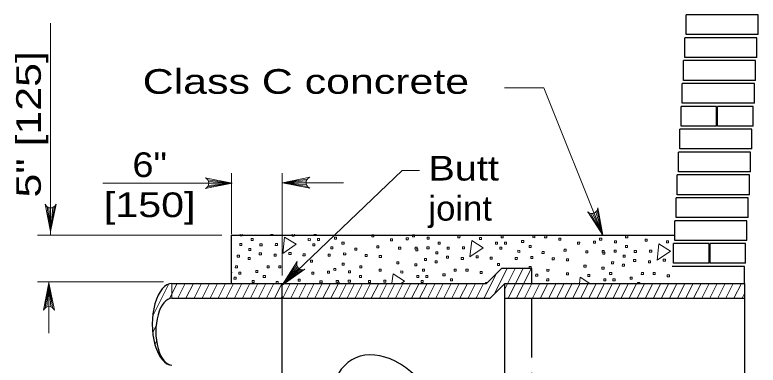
# Model space of a CAD drawing. Extents: x 750.7 to 784.7, y 860.1 to 882.1.
# Drawn here: x 758.48 to 763.303, y 876.32 to 878.591 of the extents above; entities that cross this region are included whole.
import ezdxf
from ezdxf.enums import TextEntityAlignment as Align

# ---------------------------------------------------------------- set-up
doc = ezdxf.new("R2010")
doc.units = 0
doc.header["$LTSCALE"] = 0.064
doc.linetypes.add('LONG_DASHED', pattern=[7.5, 6, -1.5])
doc.layers.add('1', color=7, linetype='Continuous', lineweight=13)

msp = doc.modelspace()

# ---------------------------------------------------------------- linework, layer by layer
at = {"layer": '1'}
for p, q in [((758.71192, 877.16183), (758.71192, 878.53658)), ((759.885, 877.16933), (759.885, 877.56492)), ((760.21358, 876.90092), (760.21358, 877.56492)), ((759.89083, 877.49983), (759.05142, 877.49983)), ((759.72867, 877.475), (759.89083, 877.49983)), ((759.7305, 877.52225), (759.89083, 877.49983)), ((759.73475, 877.48542), (759.89083, 877.49983)), ((759.736, 877.51117), (759.89083, 877.49983)), ((759.73758, 877.49983), (759.89083, 877.49983)), ((760.37617, 877.52533), (760.21583, 877.50292)), ((760.37075, 877.51425), (760.21583, 877.50292)), ((760.6125, 877.50292), (760.21583, 877.50292)), ((760.36908, 877.50292), (760.21583, 877.50292)), ((760.37192, 877.4885), (760.21583, 877.50292)), ((760.378, 877.47817), (760.21583, 877.50292)), ((758.6895, 877.34592), (758.71192, 877.18558)), ((758.73667, 877.34783), (758.71192, 877.18558)), ((758.70058, 877.3405), (758.71192, 877.18558)), ((758.72625, 877.34167), (758.71192, 877.18558)), ((758.71192, 877.33883), (758.71192, 877.18558)), ((762.21467, 877.30375), (762.29442, 877.16292)), ((762.227, 877.30283), (762.29442, 877.16292)), ((762.23808, 877.30542), (762.29442, 877.16292)), ((762.2505, 877.31333), (762.29442, 877.16292)), ((762.25792, 877.32283), (762.29442, 877.16292)), ((758.62633, 877.16183), (759.82325, 877.16183)), ((761.07608, 877.07258), (761.07625, 877.085)), ((762.29033, 877.05058), (762.2905, 877.06308)), ((760.30908, 876.96983), (760.21358, 876.83908)), ((760.31325, 876.95817), (760.21358, 876.83908)), ((760.32025, 876.94908), (760.21358, 876.83908)), ((760.33258, 876.94108), (760.21358, 876.83908)), ((760.34433, 876.93833), (760.21358, 876.83908)), ((761.52467, 876.75375), (761.60533, 876.91508)), ((761.59042, 876.78075), (761.67317, 876.94617)), ((761.659, 876.81325), (761.72542, 876.94617)), ((761.6815, 876.75375), (761.77775, 876.94617)), ((761.73383, 876.75375), (761.83, 876.94617)), ((760.56567, 876.85592), (760.56575, 876.86833)), ((760.93383, 876.91167), (760.92692, 876.85025)), ((762.14808, 876.88975), (762.14358, 876.84992)), ((762.21067, 876.84992), (762.14808, 876.88975)), ((759.44425, 876.85983), (758.62633, 876.85983)), ((758.67667, 876.69058), (758.7015, 876.85275)), ((758.68708, 876.69667), (758.7015, 876.85275)), ((758.7015, 876.527), (758.7015, 876.85983)), ((758.7015, 876.6995), (758.7015, 876.85275)), ((758.71283, 876.69792), (758.7015, 876.85275)), ((758.72392, 876.69242), (758.7015, 876.85275)), ((759.374, 876.63542), (759.47967, 876.84683)), ((759.48433, 876.7515), (759.53358, 876.84992)), ((759.49933, 876.75375), (759.49933, 876.84992)), ((759.53775, 876.75383), (759.58583, 876.84992)), ((759.59017, 876.75392), (759.63817, 876.84992)), ((759.6425, 876.754), (759.69042, 876.84992)), ((759.69483, 876.75417), (759.74267, 876.84992)), ((759.74717, 876.75425), (759.795, 876.84992)), ((759.7995, 876.75442), (759.84725, 876.84992)), ((759.85183, 876.7545), (759.89958, 876.84992)), ((759.90417, 876.75458), (759.95183, 876.84992)), ((759.9565, 876.75475), (760.00417, 876.84992)), ((760.00883, 876.75483), (760.05642, 876.84992)), ((760.06125, 876.75492), (760.10875, 876.84992)), ((760.11358, 876.75508), (760.161, 876.84992)), ((760.16592, 876.75517), (760.21325, 876.84992)), ((760.1755, 876.85325), (760.17558, 876.86117)), ((760.21358, 876.746), (760.26558, 876.84992)), ((760.26975, 876.75375), (760.31783, 876.84992)), ((760.32208, 876.75375), (760.37017, 876.84992)), ((760.37433, 876.75375), (760.42242, 876.84992)), ((760.42658, 876.75375), (760.47475, 876.84992)), ((760.47892, 876.75375), (760.527, 876.84992)), ((760.53117, 876.75375), (760.57933, 876.84992)), ((760.57017, 876.85033), (760.57025, 876.85783)), ((760.5835, 876.75375), (760.63158, 876.84992)), ((760.63575, 876.75375), (760.68383, 876.84992)), ((760.68808, 876.75375), (760.73617, 876.84992)), ((760.74033, 876.75375), (760.78842, 876.84992)), ((760.79267, 876.75375), (760.84075, 876.84992)), ((760.84492, 876.75375), (760.893, 876.84992)), ((760.89717, 876.75375), (760.94533, 876.84992)), ((760.9495, 876.75375), (760.99758, 876.84992)), ((761.00175, 876.75375), (761.04992, 876.84992)), ((761.05408, 876.75375), (761.10217, 876.84992)), ((761.10633, 876.75375), (761.15442, 876.84992)), ((761.15867, 876.75375), (761.20675, 876.84992)), ((761.21092, 876.75375), (761.259, 876.84992)), ((761.26325, 876.75375), (761.31133, 876.84992)), ((761.3155, 876.75375), (761.36358, 876.84992)), ((761.36775, 876.75375), (761.41592, 876.84992)), ((761.42008, 876.75375), (761.46817, 876.84992)), ((761.47233, 876.75375), (761.5205, 876.84992)), ((761.53258, 876.85467), (761.545, 876.85458)), ((761.53258, 876.84992), (761.53258, 876.85467)), ((761.78608, 876.75375), (761.83417, 876.84992)), ((761.83692, 876.75075), (761.8865, 876.84992)), ((761.88925, 876.75083), (761.93875, 876.84992)), ((761.94158, 876.751), (761.99108, 876.84992)), ((761.99392, 876.75108), (762.04333, 876.84992)), ((762.04625, 876.75117), (762.09558, 876.84992)), ((762.09858, 876.75133), (762.14792, 876.84992)), ((762.15092, 876.75142), (762.20017, 876.84992)), ((762.20325, 876.7515), (762.2525, 876.84992)), ((762.25567, 876.75167), (762.30475, 876.84992)), ((762.308, 876.75175), (762.35708, 876.84992)), ((762.36033, 876.75192), (762.40933, 876.84992)), ((762.41267, 876.752), (762.46167, 876.84992)), ((762.465, 876.75208), (762.51392, 876.84992)), ((762.51733, 876.75225), (762.56617, 876.84992)), ((762.52042, 876.84992), (762.5205, 876.85642)), ((762.56967, 876.75233), (762.6185, 876.84992)), ((762.622, 876.75242), (762.67075, 876.84992)), ((762.67442, 876.75258), (762.72308, 876.84992)), ((762.72675, 876.75267), (762.77533, 876.84992)), ((762.77908, 876.75275), (762.82767, 876.84992)), ((762.83142, 876.75292), (762.87992, 876.84992)), ((762.88375, 876.753), (762.93225, 876.84992)), ((762.93642, 876.75375), (762.9845, 876.84992)), ((762.98867, 876.75375), (763.03675, 876.84992)), ((763.041, 876.75375), (763.08908, 876.84992)), ((763.09325, 876.75375), (763.14133, 876.84992)), ((763.14558, 876.75375), (763.19367, 876.84992)), ((763.19783, 876.75375), (763.21333, 876.78467)), ((759.37433, 876.53142), (759.39658, 876.57592)), ((759.38817, 876.45458), (759.399, 876.47617)), ((759.4105, 876.39458), (759.41608, 876.40575)), ((759.44042, 876.34975), (759.44275, 876.35442))]:
    msp.add_line(p, q, dxfattribs=at)
at = {"layer": '1', "lineweight": 25}
for p, q in [((762.80233, 877.86975), (762.80233, 877.99783)), ((763.03992, 877.86975), (763.03992, 877.99783)), ((763.0325, 877.86975), (762.80233, 877.86975)), ((763.27, 877.86975), (763.03992, 877.86975)), ((759.885, 876.84992), (759.885, 877.16183)), ((759.885, 877.16183), (762.76183, 877.16183)), ((762.75375, 876.98017), (762.75375, 877.10825)), ((762.99125, 876.98017), (762.99125, 877.10825)), ((762.98383, 876.98017), (762.75375, 876.98017)), ((763.22142, 876.98017), (762.99125, 876.98017)), ((761.63658, 876.94617), (761.54033, 876.84992)), ((761.8345, 876.94617), (761.63658, 876.94617)), ((761.8345, 876.84992), (761.8345, 876.94617)), ((759.49933, 876.84992), (760.21358, 876.84992)), ((760.21358, 876.84992), (761.54033, 876.84992)), ((760.21367, 875.89692), (760.21358, 876.83908)), ((761.65925, 876.84992), (761.56308, 876.75375)), ((761.65933, 875.88608), (761.65925, 876.84992)), ((761.65933, 875.88617), (761.65925, 876.84992)), ((761.65925, 876.84992), (763.21333, 876.84992)), ((763.21333, 876.84992), (763.21333, 876.75367)), ((759.49933, 876.75367), (760.20417, 876.75375)), ((760.22308, 876.75375), (761.56308, 876.75375)), ((761.65925, 876.75375), (763.21333, 876.75375)), ((763.21333, 876.75375), (763.21333, 875.98958))]:
    msp.add_line(p, q, dxfattribs=at)
at = {"layer": '1', "linetype": 'LONG_DASHED', "lineweight": 25}
msp.add_line((761.8345, 875.88617), (761.8345, 876.84992), dxfattribs=at)
at = {"layer": '1', "lineweight": 25}
for points in [[(763.3025, 878.46283), (763.3025, 878.59092), (762.83475, 878.59092)], [(763.3025, 878.46283), (762.83475, 878.46283), (762.83475, 878.59092)], [(763.29433, 878.31458), (763.29433, 878.44267), (762.82667, 878.44267)], [(763.29433, 878.31458), (762.82667, 878.31458), (762.82667, 878.44267)], [(763.28625, 878.16633), (763.28625, 878.29433), (762.81858, 878.29433)], [(763.28625, 878.16633), (762.81858, 878.16633), (762.81858, 878.29433)], [(763.27817, 878.01808), (763.27817, 878.14608), (762.8105, 878.14608)], [(763.27817, 878.01808), (762.8105, 878.01808), (762.8105, 878.14608)], [(763.0325, 877.86975), (763.0325, 877.99783), (762.80233, 877.99783)], [(763.27, 877.86975), (763.27, 877.99783), (763.03992, 877.99783)], [(763.26192, 877.7215), (763.26192, 877.84958), (762.79425, 877.84958)], [(763.26192, 877.7215), (762.79425, 877.7215), (762.79425, 877.84958)], [(763.25383, 877.57325), (763.25383, 877.70133), (762.78617, 877.70133)], [(763.25383, 877.57325), (762.78617, 877.57325), (762.78617, 877.70133)], [(763.24575, 877.425), (763.24575, 877.553), (762.77808, 877.553)], [(763.24575, 877.425), (762.77808, 877.425), (762.77808, 877.553)], [(763.23758, 877.27675), (763.23758, 877.40475), (762.76992, 877.40475)], [(763.23758, 877.27675), (762.76992, 877.27675), (762.76992, 877.40475)], [(763.2295, 877.12842), (763.2295, 877.2565), (762.76183, 877.2565)], [(763.2295, 877.12842), (762.76183, 877.12842), (762.76183, 877.2565)], [(762.98383, 876.98017), (762.98383, 877.10825), (762.75375, 877.10825)], [(763.22142, 876.98017), (763.22142, 877.10825), (762.99125, 877.10825)], [(763.21333, 876.84992), (763.21333, 876.96), (762.74567, 876.96)]]:
    msp.add_lwpolyline(points, dxfattribs=at)
at = {"layer": '1'}
for points in [[(762.29442, 877.16292), (761.91233, 878.11767), (761.65675, 878.11767)], [(760.21358, 876.83908), (760.99383, 877.58225), (761.10458, 877.58225)], [(759.71375, 877.46442), (759.89083, 877.49983), (759.71375, 877.53525)], [(760.39292, 877.4675), (760.21583, 877.50292), (760.39292, 877.53833)], [(758.74733, 877.36267), (758.71192, 877.18558), (758.6765, 877.36267)], [(762.26225, 877.34058), (762.29442, 877.16292), (762.1965, 877.31458)], [(759.95483, 877.16917), (759.95467, 877.15767), (759.94108, 877.15775), (759.94117, 877.16917)], [(760.15392, 877.16867), (760.15392, 877.16675), (760.14025, 877.16683), (760.14025, 877.16867)], [(760.29333, 877.16825), (760.29325, 877.15583), (760.27958, 877.15592), (760.27975, 877.16833)], [(760.4345, 877.16792), (760.4345, 877.16733), (760.42092, 877.16742), (760.42092, 877.16792)], [(761.07625, 877.085), (761.08992, 877.08492), (761.08983, 877.07842)], [(762.2905, 877.06308), (762.30408, 877.06292), (762.30408, 877.05642)], [(760.36233, 876.94158), (760.21358, 876.83908), (760.31142, 876.99092)], [(759.885, 876.92308), (759.88675, 876.92308), (759.88658, 876.91017), (759.885, 876.91017)], [(760.56575, 876.86833), (760.57942, 876.86825), (760.57942, 876.86175)], [(760.98733, 876.85017), (761.00833, 876.86442), (760.93383, 876.91167)], [(758.66608, 876.67567), (758.7015, 876.85275), (758.73692, 876.67567)], [(760.17558, 876.86117), (760.18917, 876.86108), (760.18908, 876.85333)], [(760.57025, 876.85783), (760.58383, 876.85775), (760.58383, 876.85033)], [(762.5205, 876.85642), (762.53408, 876.85633), (762.53408, 876.84992)]]:
    msp.add_lwpolyline(points, dxfattribs=at)
for points in [[(760.79525, 877.16508), (760.80883, 877.16492), (760.80875, 877.15208), (760.79508, 877.15217)], [(761.05958, 877.16417), (761.07325, 877.164), (761.07308, 877.15108), (761.0595, 877.15125)], [(761.35467, 877.15775), (761.36825, 877.15767), (761.36808, 877.14475), (761.3545, 877.14483)], [(761.63525, 877.15842), (761.64892, 877.15825), (761.64875, 877.14533), (761.63517, 877.1455)], [(761.841, 877.15925), (761.85467, 877.15917), (761.8545, 877.14625), (761.84092, 877.14633)], [(761.9175, 877.15858), (761.93117, 877.1585), (761.931, 877.14558), (761.91742, 877.14575)], [(762.44258, 877.15767), (762.45625, 877.15758), (762.45608, 877.14467), (762.4425, 877.14475)], [(759.93967, 877.10908), (759.95325, 877.109), (759.95317, 877.09608), (759.9395, 877.09617)], [(760.01258, 877.14008), (760.02625, 877.13992), (760.02608, 877.127), (760.01242, 877.12717)], [(760.0705, 877.107), (760.08417, 877.10692), (760.084, 877.094), (760.07042, 877.09408)], [(760.17017, 877.109), (760.18375, 877.10892), (760.18367, 877.096), (760.17, 877.09608)], [(760.23008, 877.15033), (760.21817, 877.04467), (760.30458, 877.10308)], [(760.38358, 877.13983), (760.39717, 877.13975), (760.39708, 877.12683), (760.38342, 877.12692)], [(760.41242, 877.10642), (760.42608, 877.10625), (760.42592, 877.09333), (760.41233, 877.0935)], [(760.44275, 877.14008), (760.45633, 877.14), (760.45625, 877.12708), (760.44258, 877.12717)], [(760.55383, 877.15033), (760.56742, 877.15017), (760.56733, 877.13725), (760.55367, 877.13742)], [(760.6025, 877.11708), (760.61617, 877.117), (760.616, 877.10408), (760.60233, 877.10417)], [(760.91683, 877.13975), (760.93042, 877.13958), (760.93033, 877.12667), (760.91667, 877.12683)], [(761.01942, 877.14475), (761.033, 877.14467), (761.03292, 877.13175), (761.01925, 877.13192)], [(761.15542, 877.14867), (761.16908, 877.14858), (761.16892, 877.13567), (761.15533, 877.13575)], [(761.22683, 877.11808), (761.24042, 877.118), (761.24033, 877.10508), (761.22667, 877.10517)], [(761.44433, 877.12842), (761.43242, 877.02267), (761.51883, 877.08108)], [(761.494, 877.14683), (761.50758, 877.14675), (761.50742, 877.13383), (761.49383, 877.13392)], [(761.59775, 877.11783), (761.61142, 877.11775), (761.61125, 877.10483), (761.59767, 877.10492)], [(761.657, 877.11808), (761.67058, 877.118), (761.6705, 877.10508), (761.65683, 877.10517)], [(761.76808, 877.12833), (761.78167, 877.12825), (761.78158, 877.11533), (761.76792, 877.11542)], [(762.0095, 877.14308), (762.02308, 877.143), (762.023, 877.13008), (762.00933, 877.13017)], [(762.131, 877.11775), (762.14467, 877.11767), (762.1445, 877.10475), (762.13092, 877.10483)], [(762.23358, 877.12283), (762.24725, 877.12275), (762.24708, 877.10983), (762.2335, 877.10992)], [(762.27383, 877.14217), (762.2875, 877.142), (762.28733, 877.12917), (762.27367, 877.12925)], [(762.36967, 877.12667), (762.38325, 877.12658), (762.38317, 877.11367), (762.3695, 877.11375)], [(762.56883, 877.13575), (762.5825, 877.13567), (762.58233, 877.12275), (762.56875, 877.12283)], [(762.6585, 877.10642), (762.64667, 877.00067), (762.733, 877.05908)], [(762.70817, 877.12483), (762.72183, 877.12475), (762.72167, 877.11183), (762.70808, 877.11192)], [(759.99758, 877.076), (760.01117, 877.07592), (760.01108, 877.063), (759.99742, 877.06308)], [(760.52958, 877.08617), (760.54317, 877.086), (760.54308, 877.07308), (760.52942, 877.07325)], [(760.68608, 877.07792), (760.69967, 877.07775), (760.6995, 877.06483), (760.68592, 877.065)], [(760.82883, 877.09333), (760.8425, 877.09325), (760.84233, 877.08033), (760.82875, 877.08042)], [(760.96983, 877.08375), (760.98342, 877.08367), (760.98333, 877.07075), (760.96967, 877.07083)], [(761.08075, 877.0745), (761.09433, 877.07442), (761.09425, 877.0615), (761.08058, 877.06158)], [(761.15383, 877.08708), (761.1675, 877.087), (761.16733, 877.07408), (761.15375, 877.07417)], [(761.28475, 877.085), (761.29833, 877.08492), (761.29825, 877.072), (761.28458, 877.07208)], [(761.38442, 877.087), (761.398, 877.08692), (761.39783, 877.074), (761.38425, 877.07408)], [(761.62667, 877.08442), (761.64025, 877.08433), (761.64017, 877.07142), (761.6265, 877.0715)], [(761.74375, 877.06417), (761.75742, 877.06408), (761.75725, 877.05117), (761.74367, 877.05125)], [(761.81675, 877.09508), (761.83033, 877.095), (761.83025, 877.08208), (761.81658, 877.08217)], [(762.04308, 877.07133), (762.05675, 877.07125), (762.05658, 877.05833), (762.04292, 877.05842)], [(762.184, 877.06175), (762.19767, 877.06167), (762.1975, 877.04875), (762.18392, 877.04883)], [(762.36808, 877.06508), (762.38175, 877.065), (762.38158, 877.05208), (762.368, 877.05225)], [(762.441, 877.09608), (762.45467, 877.096), (762.4545, 877.08308), (762.44092, 877.08317)], [(762.499, 877.063), (762.51258, 877.06292), (762.5125, 877.05), (762.49883, 877.05008)], [(762.59858, 877.065), (762.61225, 877.06492), (762.61208, 877.052), (762.5985, 877.05208)], [(759.92325, 877.03367), (759.93683, 877.03358), (759.93667, 877.02067), (759.92308, 877.02075)], [(759.993, 877.01792), (760.00667, 877.01775), (760.0065, 877.00483), (759.99292, 877.005)], [(760.066, 877.04883), (760.07958, 877.04875), (760.0795, 877.03583), (760.06583, 877.03592)], [(760.16217, 877.03975), (760.17583, 877.03958), (760.17567, 877.02667), (760.16208, 877.02683)], [(760.25842, 877.05025), (760.27208, 877.05017), (760.27192, 877.03725), (760.25833, 877.03733)], [(760.34967, 877.04208), (760.36325, 877.042), (760.36317, 877.02908), (760.3495, 877.02917)], [(760.51242, 877.03958), (760.526, 877.0395), (760.52592, 877.02658), (760.51225, 877.02667)], [(760.61308, 877.04692), (760.62675, 877.04683), (760.62658, 877.03392), (760.613, 877.034)], [(760.75242, 877.03758), (760.766, 877.0375), (760.76592, 877.02458), (760.75225, 877.02467)], [(760.84433, 877.03017), (760.858, 877.03008), (760.85783, 877.01717), (760.84417, 877.01733)], [(761.13742, 877.01167), (761.15108, 877.01158), (761.15092, 876.99867), (761.13733, 876.99875)], [(761.21183, 877.054), (761.22542, 877.05392), (761.22533, 877.041), (761.21167, 877.04117)], [(761.28017, 877.02683), (761.29383, 877.02675), (761.29367, 877.01383), (761.28008, 877.01392)], [(761.37642, 877.01775), (761.39, 877.01767), (761.38992, 877.00475), (761.37625, 877.00483)], [(761.47267, 877.02825), (761.48633, 877.02817), (761.48617, 877.01525), (761.47258, 877.01533)], [(761.56383, 877.02008), (761.5775, 877.02), (761.57733, 877.00708), (761.56375, 877.00717)], [(761.72658, 877.01758), (761.74025, 877.0175), (761.74008, 877.00458), (761.7265, 877.00467)], [(761.82733, 877.02492), (761.84092, 877.02483), (761.84083, 877.01192), (761.82717, 877.012)], [(761.90025, 877.05592), (761.91392, 877.05583), (761.91375, 877.04292), (761.90017, 877.043)], [(761.96658, 877.01567), (761.98025, 877.0155), (761.98008, 877.00258), (761.9665, 877.00275)], [(762.29492, 877.0525), (762.30858, 877.05242), (762.30842, 877.0395), (762.29483, 877.03958)], [(762.426, 877.03208), (762.43967, 877.03192), (762.4395, 877.019), (762.42592, 877.01917)], [(759.91058, 876.96367), (759.92417, 876.96358), (759.92408, 876.95067), (759.91042, 876.95075)], [(760.11633, 876.96458), (760.12992, 876.9645), (760.12983, 876.95158), (760.11617, 876.95167)], [(760.19283, 876.96392), (760.20642, 876.96383), (760.20633, 876.95092), (760.19267, 876.951)], [(760.39758, 877.00008), (760.41117, 876.99992), (760.411, 876.987), (760.39742, 876.98717)], [(760.60308, 876.98192), (760.61667, 876.98183), (760.6165, 876.96892), (760.60292, 876.969)], [(760.71792, 876.963), (760.7315, 876.96283), (760.73142, 876.94992), (760.71775, 876.95008)], [(760.958, 876.99017), (760.97167, 876.99), (760.9715, 876.97708), (760.95792, 876.97725)], [(761.075, 876.9775), (761.08867, 876.97742), (761.0885, 876.9645), (761.07492, 876.96458)], [(761.20725, 876.99592), (761.22083, 876.99575), (761.22075, 876.98292), (761.20708, 876.983)], [(761.61175, 876.97808), (761.62542, 876.97792), (761.62525, 876.96508), (761.61167, 876.96517)], [(762.05858, 877.00825), (762.07217, 877.00808), (762.07208, 876.99525), (762.05842, 876.99533)], [(762.17225, 876.96817), (762.18592, 876.968), (762.18575, 876.95517), (762.17217, 876.95525)], [(762.35167, 876.98975), (762.36525, 876.98958), (762.36517, 876.97667), (762.3515, 876.97683)], [(762.4215, 876.97392), (762.43508, 876.97383), (762.435, 876.96092), (762.42133, 876.961)], [(762.49442, 877.00483), (762.50808, 877.00475), (762.50792, 876.99183), (762.49425, 876.992)], [(762.59067, 876.99575), (762.60425, 876.99567), (762.60408, 876.98275), (762.5905, 876.98283)], [(762.68692, 877.00625), (762.7005, 877.00617), (762.70042, 876.99325), (762.68675, 876.99342)], [(759.93225, 876.92342), (759.94592, 876.92325), (759.94575, 876.91042), (759.93217, 876.9105)], [(760.04333, 876.93358), (760.057, 876.9335), (760.05683, 876.92058), (760.04325, 876.92067)], [(760.40633, 876.923), (760.42, 876.92292), (760.41983, 876.91), (760.40617, 876.91008)], [(760.50892, 876.92808), (760.5225, 876.928), (760.52242, 876.91508), (760.50875, 876.91517)], [(760.54917, 876.94742), (760.56275, 876.94733), (760.56267, 876.93442), (760.549, 876.9345)], [(760.645, 876.932), (760.65858, 876.93192), (760.65842, 876.919), (760.64483, 876.91908)], [(760.84417, 876.94108), (760.85775, 876.941), (760.85767, 876.92808), (760.844, 876.92817)], [(760.9835, 876.93017), (760.99708, 876.93008), (760.997, 876.91717), (760.98333, 876.91725)], [(761.12475, 876.94167), (761.13842, 876.94158), (761.13825, 876.92867), (761.12467, 876.92875)], [(761.3305, 876.94258), (761.34417, 876.9425), (761.344, 876.92958), (761.33042, 876.92967)], [(761.407, 876.94192), (761.42067, 876.94183), (761.4205, 876.92892), (761.40692, 876.929)], [(761.499, 876.92642), (761.51267, 876.92625), (761.5125, 876.91342), (761.49883, 876.9135)], [(761.81725, 876.95992), (761.83092, 876.95983), (761.83075, 876.94692), (761.81717, 876.947)], [(761.93217, 876.941), (761.94575, 876.94092), (761.94558, 876.928), (761.932, 876.92808)], [(762.05842, 876.91908), (762.072, 876.919), (762.07183, 876.90608), (762.05825, 876.90617)], [(762.28925, 876.9555), (762.30283, 876.95542), (762.30275, 876.9425), (762.28908, 876.94258)], [(762.339, 876.91975), (762.35267, 876.91958), (762.3525, 876.90667), (762.33892, 876.90683)], [(762.54475, 876.92058), (762.55842, 876.9205), (762.55825, 876.90758), (762.54467, 876.90767)], [(762.62125, 876.91992), (762.63492, 876.91983), (762.63475, 876.90692), (762.62117, 876.90708)], [(759.90192, 876.88967), (759.91558, 876.88958), (759.91542, 876.87667), (759.90183, 876.87675)], [(760.01908, 876.86942), (760.03275, 876.86933), (760.03258, 876.85642), (760.019, 876.8565)], [(760.092, 876.90042), (760.10567, 876.90033), (760.1055, 876.88742), (760.09192, 876.8875)], [(760.31842, 876.87667), (760.332, 876.87658), (760.33192, 876.86367), (760.31825, 876.86375)], [(760.45933, 876.86708), (760.473, 876.86692), (760.47283, 876.85408), (760.45917, 876.85417)], [(760.64342, 876.87042), (760.657, 876.87033), (760.65692, 876.85742), (760.64325, 876.8575)], [(760.71633, 876.90142), (760.73, 876.90125), (760.72983, 876.88833), (760.71617, 876.8885)], [(760.77425, 876.86833), (760.78792, 876.86825), (760.78775, 876.85533), (760.77417, 876.85542)], [(760.87392, 876.87033), (760.8875, 876.87025), (760.88742, 876.85733), (760.87375, 876.85742)], [(761.08733, 876.90117), (761.10092, 876.90108), (761.10083, 876.88817), (761.08717, 876.88825)], [(761.11617, 876.86775), (761.12983, 876.86758), (761.12967, 876.85467), (761.11608, 876.85483)], [(761.1465, 876.90142), (761.16017, 876.90133), (761.16, 876.88842), (761.14642, 876.8885)], [(761.25758, 876.91167), (761.27125, 876.9115), (761.27108, 876.89858), (761.2575, 876.89875)], [(761.30625, 876.87842), (761.31992, 876.87833), (761.31975, 876.86542), (761.30617, 876.8655)], [(761.85917, 876.91), (761.87283, 876.90992), (761.87267, 876.897), (761.85908, 876.89708)], [(761.93058, 876.87942), (761.94417, 876.87933), (761.94408, 876.86642), (761.93042, 876.8665)], [(762.19775, 876.90817), (762.21133, 876.90808), (762.21125, 876.89517), (762.19758, 876.89525)], [(762.3015, 876.87917), (762.31517, 876.87908), (762.315, 876.86617), (762.30142, 876.86625)], [(762.36075, 876.87942), (762.37433, 876.87933), (762.37425, 876.86642), (762.36058, 876.8665)], [(762.47183, 876.88967), (762.48542, 876.8895), (762.48533, 876.87667), (762.47167, 876.87675)], [(762.71325, 876.90442), (762.72683, 876.90433), (762.72675, 876.89142), (762.71308, 876.8915)]]:
    msp.add_lwpolyline(points, close=True, dxfattribs=at)
for centre, start, end in [((759.69946, 877.49985), 292.08605, 67.91218), ((760.40721, 877.50294), 112.08782, 247.91395), ((758.71187, 877.37698), 202.08782, 337.91395), ((762.22408, 877.34088), 223.63877, 359.4649), ((760.34679, 876.97652), 157.97577, 293.8019), ((758.70154, 876.66139), 22.08782, 157.91395)]:
    msp.add_arc(centre, 0.03822, start, end, dxfattribs=at)
at = {"layer": '1', "lineweight": 25}
for centre, major_axis, ratio, start_param, end_param in [((759.49931, 876.58489), (0, 0.26506), 0.481473, 0.0000028, 3.1415955), ((759.49931, 876.53678), (0, 0.21695), 0.481473, 0.0000028, 3.1415955), ((760.20417, 876.76459), (0, -0.01086), 0.869565, 6.2831849, 7.853998), ((760.22306, 876.76459), (0, -0.01086), 0.869565, 4.7124053, 6.2831852), ((760.94913, 875.76543), (-0.25395, 0.60271), 0.592743, 4.8242854, 7.2868107)]:
    msp.add_ellipse(centre, major_axis=major_axis, ratio=ratio, start_param=start_param, end_param=end_param, dxfattribs=at)
at = {"layer": '1'}
for centre, major_axis, start_param, end_param in [((760.20417, 876.83909), (0, 0.01086), 4.7124068, 6.2831856), ((760.22306, 876.83909), (0, -0.01086), 3.1415936, 4.712406)]:
    msp.add_ellipse(centre, major_axis=major_axis, ratio=0.869565, start_param=start_param, end_param=end_param, dxfattribs=at)

# ---------------------------------------------------------------- texts
at = {"layer": '1', "width": 1.3}
msp.add_text('5" [125]', height=0.16, rotation=90, dxfattribs=at).set_placement((758.64858, 877.4065))
at = {"layer": '1'}
for s, width, p in [('Class C concrete', 1.3, (759.30958, 878.07917)), ('Butt', 1.2, (761.1635, 877.51683)), ('joint', 1.05, (761.1635, 877.25683))]:
    msp.add_text(s, height=0.16, dxfattribs=dict(at, width=width)).set_placement(p)
for s, width, p in [('6"', 1.15, (759.35487, 877.5395)), ('[150]', 1.25, (759.35483, 877.2795))]:
    msp.add_text(s, height=0.16, dxfattribs=dict(at, width=width)).set_placement(p, align=Align.CENTER)

doc.saveas('drawing.dxf')
